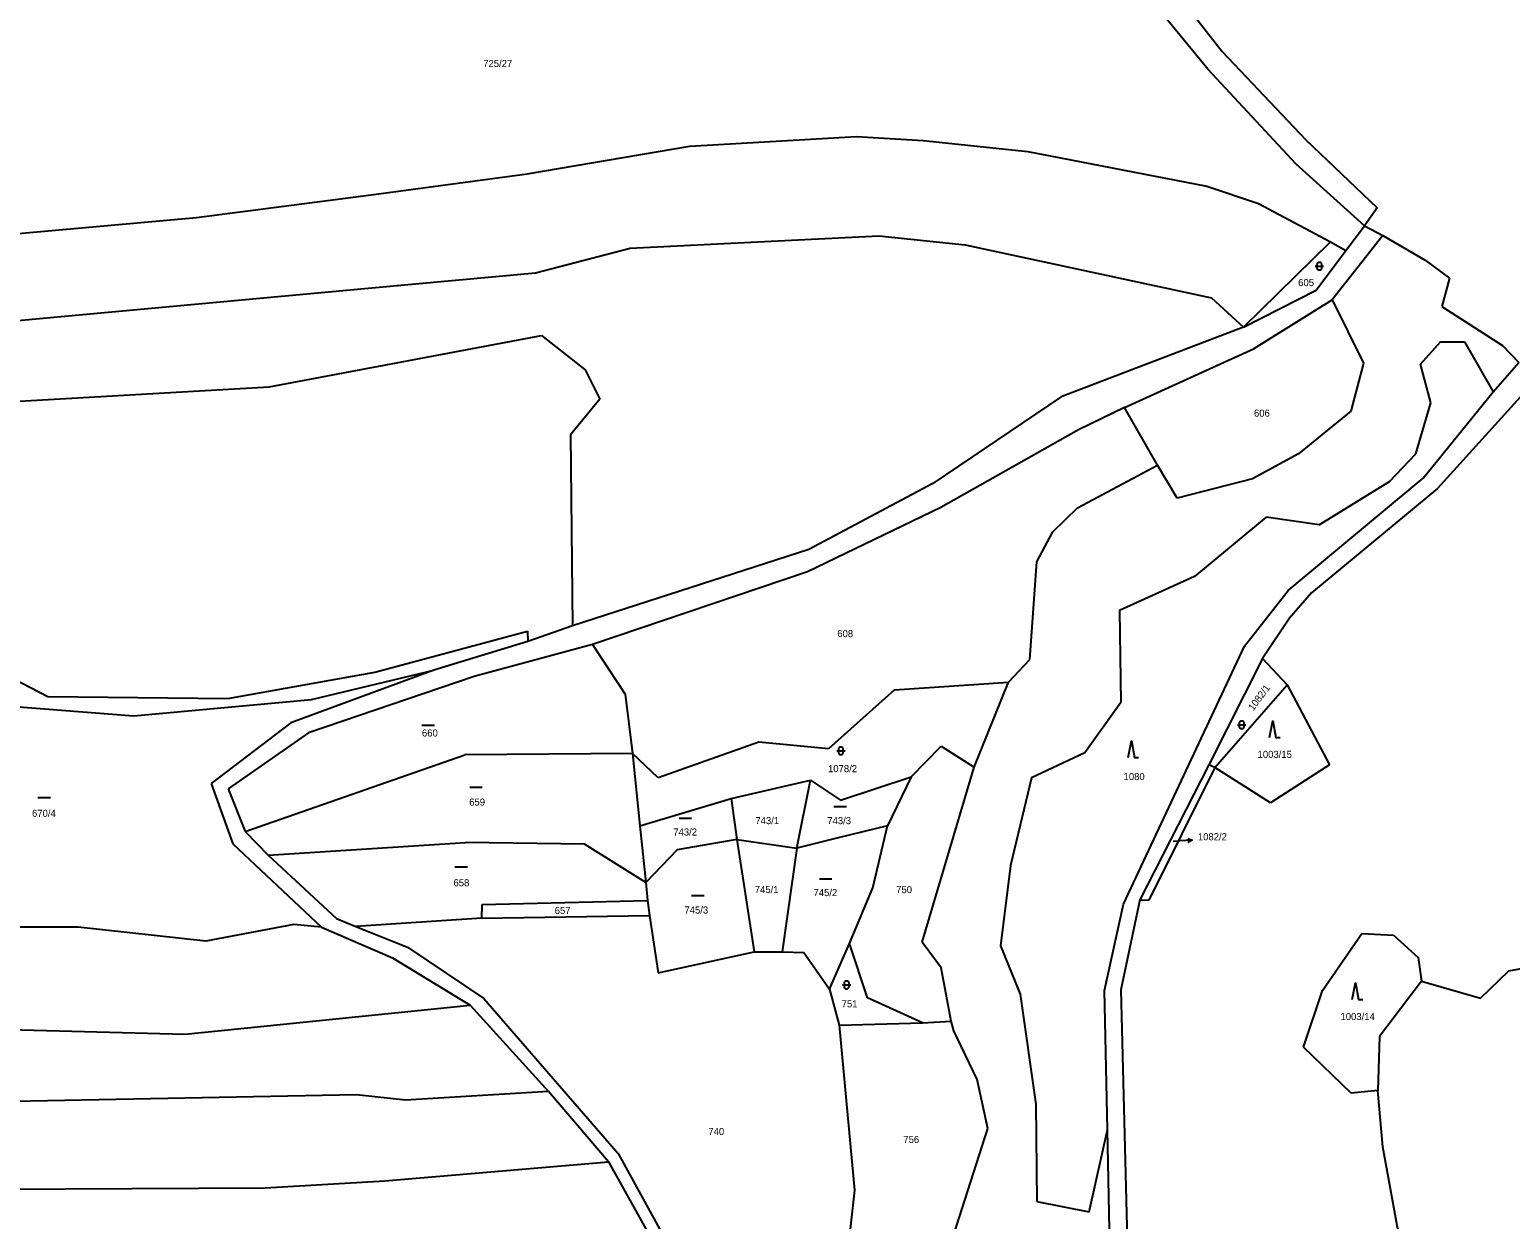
# Model space of a CAD drawing. Extents: x -799786 to -795190, y -1021716 to -1017834.
# Drawn here: x -798982.6 to -798627.9, y -1019585 to -1019300.1 of the extents above; entities that cross this region are included whole.
import ezdxf

# ---------------------------------------------------------------- set-up
doc = ezdxf.new("R2010")
doc.units = 0
for name, color, linetype in [('Default', 7, 'Continuous'), ('KN_HRANICE', 7, 'Continuous'), ('KN_KULTURY', 7, 'Continuous'), ('KN_PARCELY', 7, 'Continuous')]:
    doc.layers.add(name, color=color, linetype=linetype)

# ---------------------------------------------------------------- blocks, each defined once
blk = doc.blocks.new('308')
at = {"layer": 'Default'}
blk.add_lwpolyline([(-0.75, 0), (0, 4), (0.75, 0), (1.75, 0)], dxfattribs=at)
blk = doc.blocks.new('316')
at = {"layer": 'Default'}
for points in [[(-1, 1), (0.27, 1), (1, 1)], [(-0.5, 1.5), (-0.4, 1.79), (-0.15, 1.97), (0.16, 1.97), (0.41, 1.79), (0.51, 1.5), (0.51, 0.5), (0.41, 0.21), (0.16, 0.03), (-0.15, 0.03), (-0.4, 0.21), (-0.5, 0.5), (-0.5, 1.5)]]:
    blk.add_lwpolyline(points, dxfattribs=at)
blk = doc.blocks.new('804')
at = {"layer": 'Default'}
blk.add_line((-1.5, 0), (1.5, 0), dxfattribs=at)
blk = doc.blocks.new('10292')
at = {"layer": 'Default'}
blk.add_line((0, 3), (0, 0), dxfattribs=at)
blk.add_lwpolyline([(-0.5, 2), (0, 3), (0.5, 2)], dxfattribs=at)

msp = doc.modelspace()

# ---------------------------------------------------------------- linework, layer by layer
at = {"layer": 'KN_HRANICE'}
for p, q in [((-798712.66, -1019285.13), (-798696.86, -1019305.37)), ((-798700.33, -1019309.58), (-798717.83, -1019288.18)), ((-798696.86, -1019305.37), (-798676.85, -1019326.52)), ((-798679.17, -1019332.32), (-798700.33, -1019309.58)), ((-798824.38, -1019327.98), (-798784.49, -1019325.66)), ((-798784.49, -1019325.66), (-798768.48, -1019326.61)), ((-798863.37, -1019334.62), (-798824.38, -1019327.98)), ((-798768.48, -1019326.61), (-798743.43, -1019329.24)), ((-798743.43, -1019329.24), (-798700.56, -1019337.56)), ((-798676.85, -1019326.52), (-798659.76, -1019342.78)), ((-798662.82, -1019347.1), (-798679.17, -1019332.32)), ((-798900.7, -1019339.67), (-798863.37, -1019334.62)), ((-798942.54, -1019345.04), (-798900.7, -1019339.67)), ((-798700.56, -1019337.56), (-798688.21, -1019341.73)), ((-798688.21, -1019341.73), (-798670.93, -1019350.9)), ((-798659.76, -1019342.78), (-798662.82, -1019347.1)), ((-799021.28, -1019352.13), (-798942.54, -1019345.04)), ((-798667.24, -1019353.01), (-798662.82, -1019347.1)), ((-798662.82, -1019347.1), (-798658.39, -1019349.42)), ((-798838.7, -1019352.43), (-798779.12, -1019349.49)), ((-798779.12, -1019349.49), (-798758.47, -1019351.59)), ((-798691.75, -1019371.31), (-798670.93, -1019350.9)), ((-798670.93, -1019350.9), (-798667.24, -1019353.01)), ((-798658.39, -1019349.42), (-798670.51, -1019364.81)), ((-798658.39, -1019349.42), (-798648.3, -1019355.31)), ((-798861.35, -1019358.33), (-798838.7, -1019352.43)), ((-798758.47, -1019351.59), (-798699.41, -1019364.34)), ((-798674.41, -1019362.49), (-798667.24, -1019353.01)), ((-798648.3, -1019355.31), (-798642.4, -1019359.63)), ((-798900.6, -1019361.91), (-798861.35, -1019358.33)), ((-798642.4, -1019359.63), (-798644.3, -1019366.37)), ((-799007.83, -1019371.82), (-798900.6, -1019361.91)), ((-798699.41, -1019364.34), (-798691.75, -1019371.31)), ((-798691.75, -1019371.31), (-798674.41, -1019362.49)), ((-798689.42, -1019376.56), (-798670.51, -1019364.81)), ((-798670.51, -1019364.81), (-798663.02, -1019379.97)), ((-798644.3, -1019366.37), (-798629.75, -1019375.76)), ((-798691.75, -1019371.31), (-798735.45, -1019388.04)), ((-798925.2, -1019385.65), (-798859.9, -1019373.32)), ((-798859.9, -1019373.32), (-798849.47, -1019381.55)), ((-798649.35, -1019380.16), (-798644.61, -1019374.89)), ((-798644.61, -1019374.89), (-798638.81, -1019374.89)), ((-798638.81, -1019374.89), (-798631.96, -1019386.8)), ((-798629.75, -1019375.76), (-798625.85, -1019379.76)), ((-798720.28, -1019390.57), (-798689.42, -1019376.56)), ((-798849.47, -1019381.55), (-798845.99, -1019388.61)), ((-798663.02, -1019379.97), (-798666.08, -1019391.46)), ((-798646.92, -1019389.44), (-798649.35, -1019380.16)), ((-798631.96, -1019386.8), (-798625.85, -1019379.76)), ((-799017.43, -1019390.93), (-798925.2, -1019385.65)), ((-798621.64, -1019383.87), (-798645.34, -1019409.99)), ((-798845.99, -1019388.61), (-798852.95, -1019397.15)), ((-798735.45, -1019388.04), (-798766.21, -1019408.79)), ((-798650.51, -1019401.66), (-798646.92, -1019389.44)), ((-798648.72, -1019407.46), (-798631.96, -1019386.8)), ((-798720.28, -1019390.57), (-798731.34, -1019395.94)), ((-798712.41, -1019404.41), (-798720.28, -1019390.57)), ((-798666.08, -1019391.46), (-798678.58, -1019401.67)), ((-798731.34, -1019395.94), (-798764.32, -1019414.49)), ((-798852.95, -1019397.15), (-798852.53, -1019442.89)), ((-798678.58, -1019401.67), (-798689.65, -1019407.68)), ((-798656.83, -1019408.3), (-798650.51, -1019401.66)), ((-798731.57, -1019414.61), (-798712.41, -1019404.41)), ((-798707.67, -1019412.32), (-798712.41, -1019404.41)), ((-798689.65, -1019407.68), (-798707.67, -1019412.32)), ((-798681.05, -1019434.41), (-798648.72, -1019407.46)), ((-798766.21, -1019408.79), (-798795.9, -1019424.57)), ((-798645.34, -1019409.99), (-798675.46, -1019434.93)), ((-798673.69, -1019418.64), (-798656.83, -1019408.3)), ((-798764.32, -1019414.49), (-798796.21, -1019429.95)), ((-798737.47, -1019420.31), (-798731.57, -1019414.61)), ((-798686.33, -1019416.84), (-798703.49, -1019431.03)), ((-798673.69, -1019418.64), (-798686.33, -1019416.84)), ((-798741.25, -1019427.55), (-798737.47, -1019420.31)), ((-798795.9, -1019424.57), (-798852.53, -1019442.89)), ((-798742.93, -1019450.95), (-798741.25, -1019427.55)), ((-798796.21, -1019429.95), (-798847.69, -1019447.32)), ((-798703.49, -1019431.03), (-798721.51, -1019439.15)), ((-798691.58, -1019447.69), (-798681.05, -1019434.41)), ((-798675.46, -1019434.93), (-798680.73, -1019441.05)), ((-798721.51, -1019439.15), (-798721.17, -1019461.24)), ((-798852.53, -1019442.89), (-798863.18, -1019446.58)), ((-798680.73, -1019441.05), (-798687.26, -1019450.64)), ((-798899.85, -1019453.96), (-798863.28, -1019444.15)), ((-798863.18, -1019446.58), (-798885.73, -1019453.43)), ((-798863.28, -1019444.15), (-798863.18, -1019446.58)), ((-798847.69, -1019447.32), (-798876.03, -1019455.01)), ((-798847.69, -1019447.32), (-798839.89, -1019459.23)), ((-798720.54, -1019509.52), (-798691.58, -1019447.69)), ((-798885.73, -1019453.43), (-798919.97, -1019466.08)), ((-798915.02, -1019460.49), (-798885.73, -1019453.43)), ((-798748.1, -1019456.33), (-798742.93, -1019450.95)), ((-798687.26, -1019450.64), (-798700.1, -1019476.1)), ((-798687.26, -1019450.64), (-798681.36, -1019456.97)), ((-798988.61, -1019454.34), (-798978.18, -1019459.77)), ((-798935.07, -1019460.27), (-798899.85, -1019453.96)), ((-798876.03, -1019455.01), (-798915.74, -1019468.48)), ((-798775.39, -1019458.21), (-798748.1, -1019456.33)), ((-798756.31, -1019476.73), (-798748.1, -1019456.33)), ((-798698.62, -1019476.74), (-798681.36, -1019456.97)), ((-798681.36, -1019456.97), (-798671.22, -1019476.1)), ((-798978.18, -1019459.77), (-798935.07, -1019460.27)), ((-798957.62, -1019464.38), (-798915.02, -1019460.49)), ((-798839.89, -1019459.23), (-798838.1, -1019473.46)), ((-798775.39, -1019458.21), (-798791.19, -1019472.31)), ((-798987.14, -1019462.09), (-798957.62, -1019464.38)), ((-798721.17, -1019461.24), (-798729.81, -1019473.26)), ((-798919.97, -1019466.08), (-798939.03, -1019480.6)), ((-798915.74, -1019468.48), (-798935.03, -1019481.86)), ((-798807.84, -1019470.72), (-798831.96, -1019479.28)), ((-798791.19, -1019472.31), (-798807.84, -1019470.72)), ((-798930.92, -1019492.09), (-798878.34, -1019473.75)), ((-798838.1, -1019473.46), (-798878.34, -1019473.75)), ((-798838.1, -1019473.46), (-798836.41, -1019490.72)), ((-798831.96, -1019479.28), (-798838.1, -1019473.46)), ((-798771.38, -1019479.04), (-798764.22, -1019471.67)), ((-798764.22, -1019471.67), (-798756.31, -1019476.73)), ((-798729.81, -1019473.26), (-798742.56, -1019479.27)), ((-798768.76, -1019518.63), (-798756.31, -1019476.73)), ((-798700.1, -1019476.1), (-798716.64, -1019508.47)), ((-798698.62, -1019476.74), (-798714.43, -1019508.57)), ((-798698.62, -1019476.74), (-798700.1, -1019476.1)), ((-798685.34, -1019485.27), (-798698.62, -1019476.74)), ((-798671.22, -1019476.1), (-798685.34, -1019485.27)), ((-798939.03, -1019480.6), (-798933.88, -1019495.07)), ((-798935.03, -1019481.86), (-798930.92, -1019492.09)), ((-798814.48, -1019484.22), (-798795.51, -1019479.79)), ((-798798.78, -1019496.11), (-798795.51, -1019479.79)), ((-798795.51, -1019479.79), (-798788.35, -1019484.62)), ((-798788.35, -1019484.62), (-798771.38, -1019479.04)), ((-798771.38, -1019479.04), (-798777.07, -1019490.74)), ((-798742.56, -1019479.27), (-798747.62, -1019500.24)), ((-798836.41, -1019490.72), (-798814.48, -1019484.22)), ((-798814.48, -1019484.22), (-798813.11, -1019494.02)), ((-798930.92, -1019492.09), (-798925.44, -1019497.78)), ((-798836.41, -1019490.72), (-798834.94, -1019504.32)), ((-798777.07, -1019490.74), (-798788.88, -1019493.58)), ((-798780.55, -1019505.6), (-798777.07, -1019490.74)), ((-798933.88, -1019495.07), (-798912.6, -1019515.04)), ((-798925.44, -1019497.78), (-798878.13, -1019494.72)), ((-798849.67, -1019495.15), (-798878.13, -1019494.72)), ((-798834.94, -1019504.32), (-798849.67, -1019495.15)), ((-798813.11, -1019494.02), (-798827.44, -1019496.45)), ((-798813.11, -1019494.02), (-798809, -1019520.89)), ((-798813.11, -1019494.02), (-798798.78, -1019496.11)), ((-798798.78, -1019496.11), (-798802.26, -1019520.89)), ((-798788.88, -1019493.58), (-798798.78, -1019496.11)), ((-798925.44, -1019497.78), (-798909.01, -1019512.93)), ((-798827.44, -1019496.45), (-798834.94, -1019504.32)), ((-798747.62, -1019500.24), (-798750, -1019519.48)), ((-798834.94, -1019504.32), (-798834.52, -1019508.65)), ((-798786.14, -1019518.95), (-798780.55, -1019505.6)), ((-798874.24, -1019512.86), (-798874.14, -1019509.59)), ((-798874.14, -1019509.59), (-798834.52, -1019508.65)), ((-798834.52, -1019508.65), (-798834.1, -1019512.23)), ((-798725.07, -1019530.18), (-798720.54, -1019509.52)), ((-798716.64, -1019508.47), (-798721.17, -1019529.97)), ((-798716.64, -1019508.47), (-798714.43, -1019508.57)), ((-798909.01, -1019512.93), (-798904.38, -1019514.83)), ((-798874.24, -1019512.86), (-798904.38, -1019514.83)), ((-798874.24, -1019512.86), (-798834.1, -1019512.23)), ((-798834.1, -1019512.23), (-798831.99, -1019525.93)), ((-798970.92, -1019514.98), (-799009.92, -1019514.98)), ((-798940.36, -1019518.35), (-798970.92, -1019514.98)), ((-798919.29, -1019514.35), (-798940.36, -1019518.35)), ((-798912.6, -1019515.04), (-798919.29, -1019514.35)), ((-798912.6, -1019515.04), (-798895.63, -1019522.31)), ((-798904.38, -1019514.83), (-798892.05, -1019519.78)), ((-798672.88, -1019530.17), (-798663.4, -1019516.52)), ((-798663.4, -1019516.52), (-798655.86, -1019516.94)), ((-798655.86, -1019516.94), (-798649.91, -1019522.27)), ((-798892.05, -1019519.78), (-798873.74, -1019532.08)), ((-798831.99, -1019525.93), (-798809, -1019520.89)), ((-798809, -1019520.89), (-798802.26, -1019520.89)), ((-798802.26, -1019520.89), (-798797.1, -1019521.1)), ((-798797.1, -1019521.1), (-798790.99, -1019529.81)), ((-798790.99, -1019529.81), (-798786.14, -1019518.95)), ((-798781.82, -1019531.92), (-798786.14, -1019518.95)), ((-798764.23, -1019524.75), (-798768.76, -1019518.63)), ((-798750, -1019519.48), (-798745.29, -1019531.06)), ((-798895.63, -1019522.31), (-798877, -1019533.66)), ((-798761.81, -1019537.48), (-798764.23, -1019524.75)), ((-798649.91, -1019522.27), (-798649.12, -1019527.91)), ((-798628.24, -1019525.47), (-798620.45, -1019523.99)), ((-798649.12, -1019527.91), (-798659.24, -1019541.19)), ((-798649.12, -1019527.91), (-798634.99, -1019532.01)), ((-798634.99, -1019532.01), (-798628.24, -1019525.47)), ((-798790.99, -1019529.81), (-798788.67, -1019538.45)), ((-798745.29, -1019531.06), (-798741.5, -1019557.42)), ((-798724.33, -1019563.53), (-798725.07, -1019530.18)), ((-798721.17, -1019529.97), (-798719.63, -1019589.9)), ((-798677.41, -1019543.72), (-798672.88, -1019530.17)), ((-798945.32, -1019540.6), (-798877, -1019533.66)), ((-798877, -1019533.66), (-798858.25, -1019554.32)), ((-798873.74, -1019532.08), (-798841.6, -1019569.19)), ((-798768.65, -1019537.93), (-798781.82, -1019531.92)), ((-798788.67, -1019538.45), (-798768.65, -1019537.93)), ((-798788.67, -1019538.45), (-798784.99, -1019577.96)), ((-798768.65, -1019537.93), (-798761.81, -1019537.48)), ((-798761.18, -1019539.8), (-798761.81, -1019537.48)), ((-798996.61, -1019539.23), (-798945.32, -1019540.6)), ((-798755.59, -1019551.5), (-798761.18, -1019539.8)), ((-798659.24, -1019541.19), (-798659.64, -1019554.1)), ((-798665.96, -1019554.77), (-798677.41, -1019543.72)), ((-798753.06, -1019563.2), (-798755.59, -1019551.5)), ((-798904.22, -1019555.15), (-799000.93, -1019557.04)), ((-798892.52, -1019556.41), (-798904.22, -1019555.15)), ((-798858.25, -1019554.32), (-798892.52, -1019556.41)), ((-798843.91, -1019571.19), (-798858.25, -1019554.32)), ((-798659.64, -1019554.1), (-798665.96, -1019554.77)), ((-798658.38, -1019567.59), (-798659.64, -1019554.1)), ((-798741.5, -1019557.42), (-798741.29, -1019580.72)), ((-798763.39, -1019595.46), (-798753.06, -1019563.2)), ((-798728.75, -1019583.14), (-798724.33, -1019563.53)), ((-798723.85, -1019587.37), (-798724.33, -1019563.53)), ((-798841.6, -1019569.19), (-798827.09, -1019595.48)), ((-798653.74, -1019592.96), (-798658.38, -1019567.59)), ((-798897.47, -1019575.71), (-798843.91, -1019571.19)), ((-798843.91, -1019571.19), (-798832.55, -1019591.58)), ((-798990.03, -1019577.71), (-798926.11, -1019577.44)), ((-798926.11, -1019577.44), (-798897.47, -1019575.71)), ((-798784.99, -1019577.96), (-798786.52, -1019592.32)), ((-798741.29, -1019580.72), (-798728.75, -1019583.14))]:
    msp.add_line(p, q, dxfattribs=at)
at = {"layer": 'KN_PARCELY'}
msp.add_line((-798708.64, -1019494.38), (-798707.1, -1019494.32), dxfattribs=at)

# ---------------------------------------------------------------- block references
at = {"layer": 'KN_KULTURY'}
for name, p in [('316', (-798673.61, -1019357.72)), ('804', (-798887.08, -1019466.65)), ('316', (-798692.21, -1019467.54)), ('308', (-798684.77, -1019469.61)), ('308', (-798718.65, -1019474.41)), ('316', (-798788.23, -1019473.78)), ('804', (-798875.62, -1019481.47)), ('804', (-798979.06, -1019483.92)), ('804', (-798825.47, -1019488.9)), ('804', (-798788.39, -1019486.1)), ('804', (-798879.2, -1019500.54)), ('804', (-798791.88, -1019503.46)), ('804', (-798822.48, -1019507.45)), ('316', (-798786.86, -1019529.84)), ('308', (-798664.97, -1019532.31))]:
    msp.add_blockref(name, p, dxfattribs=at)
at = {"layer": 'KN_PARCELY', "rotation": -87.73045600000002}
msp.add_blockref('10292', (-798707.1, -1019494.32), dxfattribs=at)

# ---------------------------------------------------------------- texts
at = {"layer": 'KN_PARCELY'}
for s, height, p in [('725/27', 1.7, (-798873.9, -1019309.05)), ('605', 1.7, (-798678.68, -1019361.51)), ('606', 1.7, (-798689.27, -1019392.78)), ('608', 1.7, (-798789.08, -1019445.56)), ('660', 1.7, (-798888.57, -1019469.35)), ('1003/15', 1.7, (-798688.41, -1019474.48)), ('1078/2', 1.7, (-798791.3, -1019477.89)), ('1080', 1.7, (-798720.51, -1019479.79)), ('659', 1.7, (-798877.25, -1019485.9)), ('670/4', 1.7, (-798981.97, -1019488.6)), ('743/1', 1.7, (-798808.71, -1019490.34)), ('743/3', 1.7, (-798791.48, -1019490.34)), ('743/2', 1.7, (-798828.37, -1019493.07)), ('1082/2', 1.7, (-798702.71, -1019494.2)), ('1082/2', 0.1, (-798708.62, -1019494.38)), ('658', 1.7, (-798881.02, -1019505.22)), ('745/1', 1.7, (-798808.85, -1019506.85)), ('745/2', 1.7, (-798794.78, -1019507.57)), ('750', 1.7, (-798774.97, -1019506.85)), ('657', 1.7, (-798856.77, -1019511.87)), ('745/3', 1.7, (-798825.7, -1019511.75)), ('751', 1.7, (-798788.04, -1019534.2)), ('1003/14', 1.7, (-798668.55, -1019537.25)), ('740', 1.7, (-798819.97, -1019564.78)), ('756', 1.7, (-798773.27, -1019566.69))]:
    msp.add_text(s, height=height, dxfattribs=at).set_placement(p)
msp.add_text('1082/1', height=1.7, rotation=53.285, dxfattribs=at).set_placement((-798689.45, -1019463.31))

doc.saveas('drawing.dxf')
